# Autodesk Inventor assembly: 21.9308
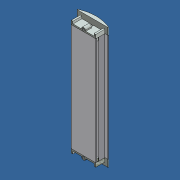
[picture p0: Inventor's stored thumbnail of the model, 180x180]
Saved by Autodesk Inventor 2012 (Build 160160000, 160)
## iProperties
Created: 2014-08
Part Number: 21.9308
Document SubType Name: Assembly
Designer: Admin
Description: FLUSH PULL 160 AL
Author: Admin
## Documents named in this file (4)
- C:\Andys Backup Data\ANDY'S INVENTOR\INVENTOR LIBRARIES\PARTS LIBRARY\HANDLES LOCKS STOPS\21.9308 FLUSH PULL 160 AL.iam
- C:\Andys Backup Data\ANDY'S INVENTOR\INVENTOR LIBRARIES\PARTS LIBRARY\HANDLES LOCKS STOPS\SUBCOMPONENTS\21.9308 FLUSH PULL 160 AL PROFILE.ipt
- C:\Andys Backup Data\ANDY'S INVENTOR\INVENTOR LIBRARIES\PARTS LIBRARY\HANDLES LOCKS STOPS\SUBCOMPONENTS\21.9308 FLUSH PULL 160 AL CAP RIGHT.ipt
- C:\Andys Backup Data\ANDY'S INVENTOR\INVENTOR LIBRARIES\PARTS LIBRARY\HANDLES LOCKS STOPS\SUBCOMPONENTS\21.9308 FLUSH PULL 160 AL CAP LEFT.ipt
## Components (3 placed, 3 different names)
1. 21.9308 FLUSH PULL 160 AL PROFILE:1 — Flush:1
2. 21.9308 FLUSH PULL 160 AL CAP RIGHT:1 — Flush:1
3. 21.9308 FLUSH PULL 160 AL CAP LEFT:1
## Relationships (1: Flush 1)
- Flush:1: 21.9308 FLUSH PULL 160 AL PROFILE:1 ↔ 21.9308 FLUSH PULL 160 AL CAP RIGHT:1
